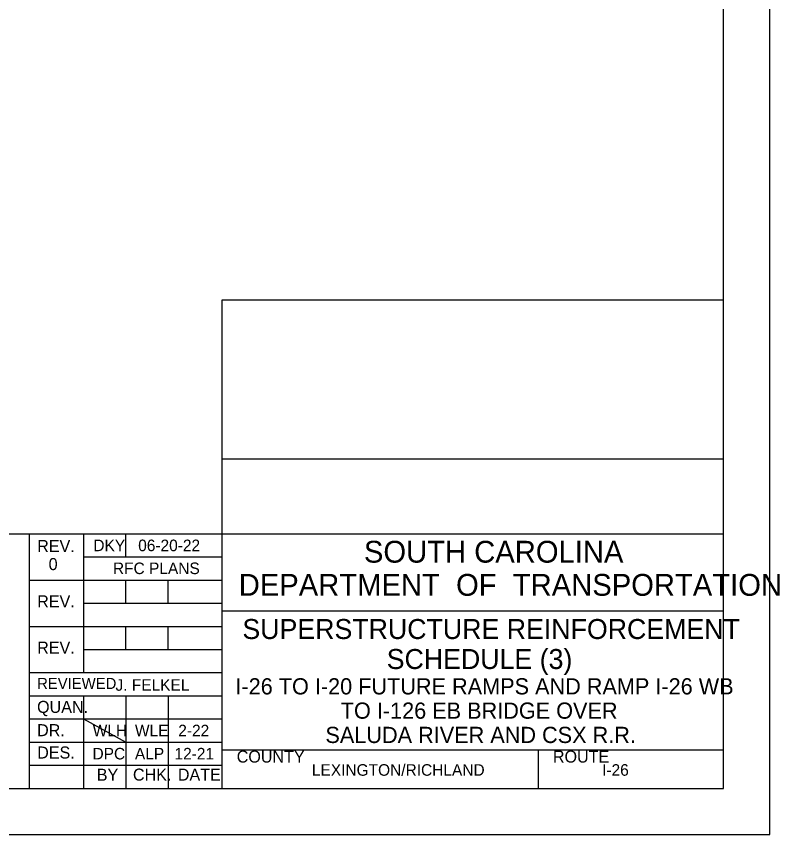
# Model space of a CAD drawing. Extents: x -133.1 to -97, y -1.7 to 20.6.
# Drawn here: x -105.28 to -97.03, y -1.69 to 7.15 of the extents above; entities that cross this region are included whole.
import ezdxf

# ---------------------------------------------------------------- set-up
doc = ezdxf.new("R2010")
doc.units = 0
for name, color, linetype in [('BR_BORDER LINES', 7, 'Continuous'), ('BR_TEXT', 7, 'Continuous'), ('Level 31', 7, 'Continuous')]:
    doc.layers.add(name, color=color, linetype=linetype)

msp = doc.modelspace()

# ---------------------------------------------------------------- linework, layer by layer
at = {"layer": 'BR_BORDER LINES'}
for p, q in [((-97.6416, -1.191), (-97.6416, 19.8089)), ((-103.0585, -1.191), (-103.0585, 4.0855)), ((-103.0585, 4.0855), (-97.6416, 4.0855)), ((-103.0583, 2.3708), (-97.6416, 2.3708)), ((-110.5071, 1.5591), (-105.1419, 1.5591)), ((-105.1419, -1.191), (-105.1419, 1.5591)), ((-105.1419, 1.5591), (-97.6416, 1.5591)), ((-104.5585, 1.5591), (-104.5585, 0.059)), ((-104.1002, 1.3091), (-104.1002, 1.5591)), ((-104.5585, 1.3091), (-103.0585, 1.3091)), ((-105.1419, 1.0591), (-103.0585, 1.0591)), ((-104.1002, 0.809), (-104.1002, 1.0591)), ((-103.6418, 0.809), (-103.6418, 1.0591)), ((-104.5585, 0.809), (-103.0585, 0.809)), ((-103.0585, 0.7257), (-103.0585, 0.7257)), ((-103.0585, 0.7257), (-97.6414, 0.7257)), ((-105.1419, 0.559), (-103.0585, 0.559)), ((-104.1002, 0.309), (-104.1002, 0.559)), ((-103.6418, 0.309), (-103.6418, 0.559)), ((-104.5585, 0.309), (-103.0585, 0.309)), ((-105.1419, 0.059), (-103.0585, 0.059)), ((-105.1419, -0.191), (-103.0585, -0.191)), ((-104.5585, -0.191), (-104.5585, -1.191)), ((-104.1002, -0.191), (-104.1002, -1.191)), ((-103.6418, -0.191), (-103.6418, -1.191)), ((-105.1419, -0.441), (-103.0585, -0.441)), ((-105.1419, -0.691), (-103.0585, -0.691)), ((-103.0585, -0.7744), (-97.6416, -0.7744)), ((-102.9609, -0.7744), (-97.6416, -0.7744)), ((-99.6417, -1.191), (-99.6417, -0.7744)), ((-105.1419, -0.941), (-103.0585, -0.941)), ((-131.3076, -1.191), (-97.6416, -1.191))]:
    msp.add_line(p, q, dxfattribs=at)
at = {"layer": 'Level 31'}
for p, q in [((-100.3498, 0.2855), (-100.3498, 0.2855)), ((-104.5585, -0.441), (-104.1002, -0.691))]:
    msp.add_line(p, q, dxfattribs=at)
msp.add_lwpolyline([(-133.1409, -1.691), (-97.141, -1.691), (-97.141, 20.309), (-133.1409, 20.309)], close=True, dxfattribs=at)

# ---------------------------------------------------------------- texts
at = {"layer": 'BR_TEXT'}
for s, height, p in [('REV.', 0.13001, (-105.0572, 1.362)), ('DKY', 0.12499, (-104.4502, 1.3715)), ('06-20-22', 0.12499, (-103.9658, 1.3715)), ('SOUTH CAROLINA', 0.23587, (-101.5266, 1.2475)), ('0', 0.13, (-104.9333, 1.167)), ('RFC PLANS', 0.12499, (-104.2386, 1.124)), ('DEPARTMENT  OF  TRANSPORTATION', 0.23587, (-102.8793, 0.8897)), ('REV.', 0.13001, (-105.0572, 0.7645)), ('SUPERSTRUCTURE REINFORCEMENT', 0.216, (-102.84, 0.4225)), ('REV.', 0.13001, (-105.0572, 0.2644)), ('SCHEDULE (3)', 0.216, (-101.2806, 0.0985)), ('REVIEWED', 0.12, (-105.0579, -0.1175)), ('I-26 TO I-20 FUTURE RAMPS AND RAMP I-26 WB', 0.175, (-102.915, -0.1761)), ('J. FELKEL', 0.125, (-104.2114, -0.1366)), ('QUAN.', 0.13001, (-105.0585, -0.3758)), ('TO I-126 EB BRIDGE OVER', 0.175, (-101.777, -0.4386)), ('DR.', 0.13001, (-105.0583, -0.6274)), ('WLH', 0.12499, (-104.4571, -0.6286)), ('WLE', 0.12499, (-104.0008, -0.6286)), ('2-22', 0.12499, (-103.5328, -0.6286)), ('SALUDA RIVER AND CSX R.R.', 0.175, (-101.9427, -0.7011)), ('DES.', 0.13001, (-105.0572, -0.8687)), ('DPC', 0.12499, (-104.4595, -0.8786)), ('ALP', 0.12499, (-104.0012, -0.8786)), ('12-21', 0.12499, (-103.5737, -0.8786)), ('COUNTY', 0.13001, (-102.9012, -0.9127)), ('ROUTE', 0.13001, (-99.4844, -0.9127)), ('LEXINGTON/RICHLAND', 0.124995, (-102.089, -1.0548)), ('I-26', 0.12499, (-98.953, -1.0548)), ('BY', 0.13001, (-104.4132, -1.109)), ('CHK.', 0.13001, (-104.0224, -1.1077)), ('DATE', 0.13001, (-103.5372, -1.1076))]:
    msp.add_text(s, height=height, dxfattribs=at).set_placement(p)

doc.saveas('drawing.dxf')
